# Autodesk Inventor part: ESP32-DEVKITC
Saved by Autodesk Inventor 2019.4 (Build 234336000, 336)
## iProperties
Created: 2020-04
Part Number: ESP32-DEVKITC
Material: Generic
Document SubType Name: Modeling
Designer: Administrator
Density: 1 g/cm^3
Appearance: Default
Title: MODULE_ESP32-DEVKITC
Author: Administrator
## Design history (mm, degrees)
